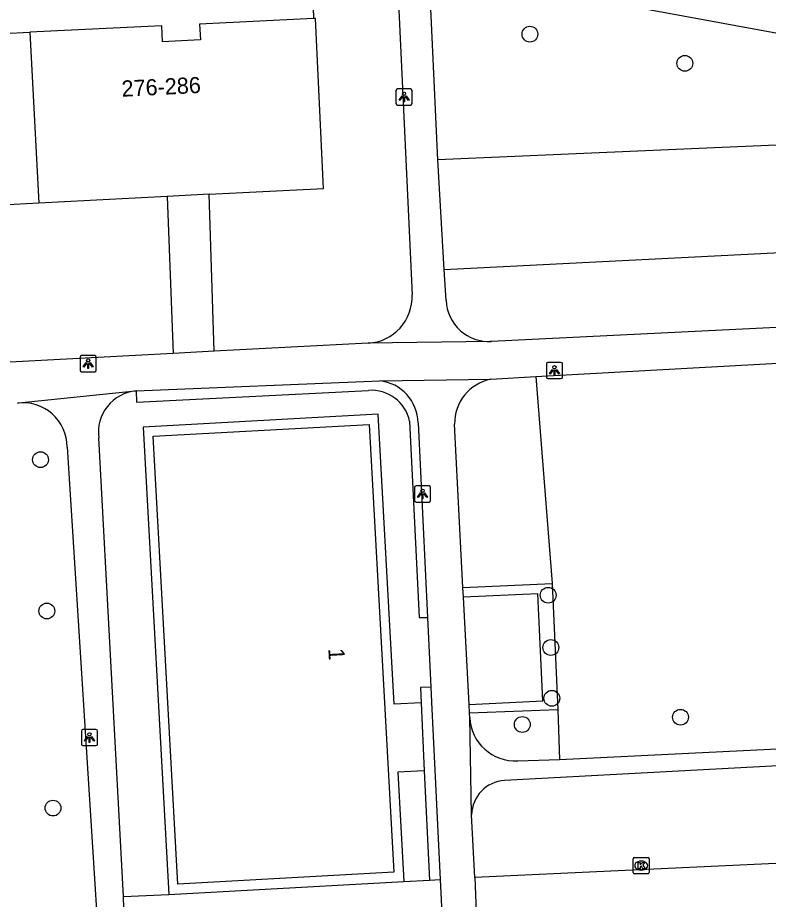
# Model space of a CAD drawing. Extents: x 161084 to 161928, y 385355 to 386522.
# Drawn here: x 161295.2 to 161341.7, y 385391.3 to 385445.9 of the extents above; entities that cross this region are included whole.
import ezdxf

# ---------------------------------------------------------------- set-up
doc = ezdxf.new("R2010")
doc.units = 0
for name, color, linetype in [('IMGEO_Boom', 7, 'Continuous'), ('IMGEO_Groenvoorziening', 7, 'Continuous'), ('IMGEO_Haag', 7, 'Continuous'), ('IMGEO_Kolk', 7, 'Continuous'), ('IMGEO_Lichtpunt', 7, 'Continuous'), ('IMGEO_Pand', 7, 'Continuous'), ('IMGEO_Pand_nummerreeks', 7, 'Continuous'), ('IMGEO_Parkeervlak_open', 7, 'Continuous'), ('IMGEO_Rijbaan_lokaal_open', 7, 'Continuous'), ('IMGEO_Voetpad_open', 7, 'Continuous')]:
    doc.layers.add(name, color=color, linetype=linetype)

msp = doc.modelspace()

# ---------------------------------------------------------------- linework, layer by layer
at = {"layer": 'IMGEO_Boom'}
for centre in [(161326.925, 385444.923), (161336.513, 385443.114), (161296.638, 385418.575), (161328.055, 385410.181), (161297.028, 385409.204), (161328.221, 385406.942), (161328.284, 385403.801), (161326.452, 385402.175), (161336.247, 385402.627), (161297.406, 385397.002)]:
    msp.add_circle(centre, 0.489, dxfattribs=at)
at = {"layer": 'IMGEO_Groenvoorziening'}
for points in [[(161370.714, 385439.291), (161321.228, 385437.144)], [(161321.624, 385430.341), (161370.59, 385432.827)], [(161327.282, 385423.72), (161328.3, 385410.901)], [(161328.656, 385403.078), (161328.751, 385400.019)]]:
    msp.add_lwpolyline(points, dxfattribs=at)
at = {"layer": 'IMGEO_Haag'}
for points in [[(161322.781, 385410.662), (161328.3, 385410.901)], [(161328.3, 385410.901), (161328.656, 385403.078)], [(161328.656, 385403.078), (161323.183, 385402.882)]]:
    msp.add_lwpolyline(points, dxfattribs=at)
at = {"layer": 'IMGEO_Kolk'}
for p, q in [((161333.388, 385393.94), (161334.24, 385393.94)), ((161333.313, 385393.014), (161333.313, 385393.866)), ((161333.801, 385393.72), (161333.826, 385393.72)), ((161334.314, 385393.866), (161334.314, 385393.014)), ((161334.24, 385392.94), (161333.388, 385392.94)), ((161333.824, 385393.16), (161333.799, 385393.16))]:
    msp.add_line(p, q, dxfattribs=at)
for points in [[(161333.388, 385393.94), (161334.24, 385393.94)], [(161333.313, 385393.014), (161333.313, 385393.866)], [(161333.634, 385393.64), (161333.757, 385393.64), (161333.757, 385393.489), (161333.887, 385393.64), (161334.051, 385393.64), (161333.905, 385393.489), (161334.058, 385393.24), (161333.906, 385393.24), (161333.821, 385393.404), (161333.757, 385393.337), (161333.757, 385393.24), (161333.634, 385393.24), (161333.634, 385393.64)], [(161334.314, 385393.866), (161334.314, 385393.014)], [(161334.24, 385392.94), (161333.388, 385392.94)]]:
    msp.add_lwpolyline(points, dxfattribs=at)
for centre, start, end in [((161333.39, 385393.864), 91.552, 178.448), ((161333.39, 385393.864), 91.552, 178.448), ((161334.238, 385393.864), 1.552, 88.448), ((161334.238, 385393.864), 1.552, 88.448), ((161333.39, 385393.016), 181.552, 268.448), ((161333.39, 385393.016), 181.552, 268.448), ((161334.238, 385393.016), 271.552, 358.448), ((161334.238, 385393.016), 271.552, 358.448)]:
    msp.add_arc(centre, 0.0765, start, end, dxfattribs=at)
for centre, major_axis, ratio, start_param, end_param in [((161333.8, 385393.44), (-0.387, 0.002), 0.722429, 4.712389, 7.853982), ((161333.825, 385393.44), (-0.39, 0.002), 0.717154, 1.570796, 4.712389)]:
    msp.add_ellipse(centre, major_axis=major_axis, ratio=ratio, start_param=start_param, end_param=end_param, dxfattribs=at)
at = {"layer": 'IMGEO_Lichtpunt'}
for p, q in [((161318.636, 385441.434), (161318.636, 385440.627)), ((161318.636, 385441.434), (161318.636, 385440.627)), ((161319.538, 385441.529), (161318.73, 385441.529)), ((161319.538, 385441.529), (161318.73, 385441.529)), ((161319.632, 385440.627), (161319.632, 385441.434)), ((161319.632, 385440.627), (161319.632, 385441.434)), ((161318.73, 385440.533), (161319.538, 385440.533)), ((161318.73, 385440.533), (161319.538, 385440.533)), ((161299.99, 385425.019), (161299.182, 385425.019)), ((161299.99, 385425.019), (161299.182, 385425.019)), ((161299.088, 385424.924), (161299.088, 385424.117)), ((161299.088, 385424.924), (161299.088, 385424.117)), ((161300.084, 385424.117), (161300.084, 385424.924)), ((161300.084, 385424.117), (161300.084, 385424.924)), ((161327.944, 385424.501), (161327.944, 385423.694)), ((161327.944, 385424.501), (161327.944, 385423.694)), ((161328.846, 385424.596), (161328.038, 385424.596)), ((161328.846, 385424.596), (161328.038, 385424.596)), ((161328.94, 385423.694), (161328.94, 385424.501)), ((161328.94, 385423.694), (161328.94, 385424.501)), ((161299.182, 385424.023), (161299.99, 385424.023)), ((161299.182, 385424.023), (161299.99, 385424.023)), ((161328.038, 385423.6), (161328.846, 385423.6)), ((161328.038, 385423.6), (161328.846, 385423.6)), ((161319.783, 385416.851), (161319.783, 385416.044)), ((161319.783, 385416.851), (161319.783, 385416.044)), ((161320.685, 385416.946), (161319.877, 385416.946)), ((161320.685, 385416.946), (161319.877, 385416.946)), ((161320.779, 385416.044), (161320.779, 385416.851)), ((161320.779, 385416.044), (161320.779, 385416.851)), ((161319.877, 385415.95), (161320.685, 385415.95)), ((161319.877, 385415.95), (161320.685, 385415.95)), ((161299.165, 385401.773), (161299.165, 385400.966)), ((161299.165, 385401.773), (161299.165, 385400.966)), ((161300.067, 385401.868), (161299.259, 385401.868)), ((161300.067, 385401.868), (161299.259, 385401.868)), ((161300.161, 385400.966), (161300.161, 385401.773)), ((161300.161, 385400.966), (161300.161, 385401.773)), ((161299.259, 385400.872), (161300.067, 385400.872)), ((161299.259, 385400.872), (161300.067, 385400.872))]:
    msp.add_line(p, q, dxfattribs=at)
for points in [[(161319.01, 385441.098), (161319.049, 385441.07), (161318.861, 385440.808), (161318.823, 385440.835), (161319.01, 385441.098)], [(161319.112, 385441.05), (161319.159, 385441.05), (161319.159, 385440.728), (161319.112, 385440.728), (161319.112, 385441.05)], [(161319.222, 385441.07), (161319.26, 385441.097), (161319.447, 385440.835), (161319.408, 385440.807), (161319.222, 385441.07)], [(161299.462, 385424.588), (161299.501, 385424.56), (161299.313, 385424.298), (161299.275, 385424.325), (161299.462, 385424.588)], [(161299.564, 385424.54), (161299.611, 385424.54), (161299.611, 385424.218), (161299.564, 385424.218), (161299.564, 385424.54)], [(161299.674, 385424.56), (161299.712, 385424.587), (161299.899, 385424.325), (161299.86, 385424.297), (161299.674, 385424.56)], [(161328.318, 385424.165), (161328.357, 385424.137), (161328.169, 385423.875), (161328.131, 385423.902), (161328.318, 385424.165)], [(161328.42, 385424.117), (161328.467, 385424.117), (161328.467, 385423.795), (161328.42, 385423.795), (161328.42, 385424.117)], [(161328.53, 385424.137), (161328.568, 385424.164), (161328.755, 385423.902), (161328.716, 385423.874), (161328.53, 385424.137)], [(161320.157, 385416.515), (161320.196, 385416.487), (161320.008, 385416.225), (161319.97, 385416.252), (161320.157, 385416.515)], [(161320.259, 385416.467), (161320.306, 385416.467), (161320.306, 385416.145), (161320.259, 385416.145), (161320.259, 385416.467)], [(161320.369, 385416.487), (161320.407, 385416.514), (161320.594, 385416.252), (161320.555, 385416.224), (161320.369, 385416.487)], [(161299.539, 385401.437), (161299.578, 385401.409), (161299.39, 385401.147), (161299.352, 385401.174), (161299.539, 385401.437)], [(161299.641, 385401.389), (161299.688, 385401.389), (161299.688, 385401.067), (161299.641, 385401.067), (161299.641, 385401.389)], [(161299.751, 385401.409), (161299.789, 385401.436), (161299.976, 385401.174), (161299.937, 385401.146), (161299.751, 385401.409)]]:
    msp.add_lwpolyline(points, dxfattribs=at)
for centre in [(161319.135, 385441.232), (161299.587, 385424.722), (161328.443, 385424.299), (161320.282, 385416.649), (161299.664, 385401.571)]:
    msp.add_circle(centre, 0.0994, dxfattribs=at)
for centre, start, end in [((161318.73, 385441.434), 90, 180), ((161318.73, 385441.434), 90, 180), ((161319.538, 385441.434), 0, 90), ((161319.538, 385441.434), 0, 90), ((161318.73, 385440.627), 180, 270), ((161318.73, 385440.627), 180, 270), ((161319.538, 385440.627), 270, 0), ((161319.538, 385440.627), 270, 360), ((161299.182, 385424.924), 90, 180), ((161299.182, 385424.924), 90, 180), ((161299.99, 385424.924), 0, 90), ((161299.99, 385424.924), 0, 90), ((161328.038, 385424.501), 90, 180), ((161328.038, 385424.501), 90, 180), ((161328.846, 385424.501), 0, 90), ((161328.846, 385424.501), 0, 90), ((161299.182, 385424.117), 180, 270), ((161299.182, 385424.117), 180, 270), ((161299.99, 385424.117), 270, 0), ((161299.99, 385424.117), 270, 360), ((161328.038, 385423.694), 180, 270), ((161328.038, 385423.694), 180, 270), ((161328.846, 385423.694), 270, 0), ((161328.846, 385423.694), 270, 360), ((161319.877, 385416.851), 90, 180), ((161319.877, 385416.851), 90, 180), ((161320.685, 385416.851), 0, 90), ((161320.685, 385416.851), 0, 90), ((161319.877, 385416.044), 180, 270), ((161319.877, 385416.044), 180, 270), ((161320.685, 385416.044), 270, 0), ((161320.685, 385416.044), 270, 360), ((161299.259, 385401.773), 90, 180), ((161299.259, 385401.773), 90, 180), ((161300.067, 385401.773), 0, 90), ((161300.067, 385401.773), 0, 90), ((161299.259, 385400.966), 180, 270), ((161299.259, 385400.966), 180, 270), ((161300.067, 385400.966), 270, 0), ((161300.067, 385400.966), 270, 360)]:
    msp.add_arc(centre, 0.0946, start, end, dxfattribs=at)
at = {"layer": 'IMGEO_Pand'}
for points in [[(161313.53, 385445.893), (161306.48, 385445.551), (161306.528, 385444.567), (161304.195, 385444.453), (161304.147, 385445.437), (161295.975, 385445.04)], [(161307.077, 385435.005), (161314.158, 385435.375), (161313.659, 385445.899), (161313.53, 385445.893)], [(161277.131, 385444.184), (161285.396, 385444.625), (161285.452, 385443.586), (161287.852, 385443.714), (161287.803, 385444.643), (161295.975, 385445.04)], [(161295.975, 385445.04), (161296.529, 385434.453)], [(161304.483, 385434.869), (161296.529, 385434.453)], [(161307.077, 385435.005), (161304.483, 385434.869)], [(161296.529, 385434.453), (161288.111, 385434.013)], [(161316.966, 385420.763), (161318.493, 385393.025), (161305.134, 385392.29), (161303.617, 385420.029), (161316.966, 385420.763)]]:
    msp.add_lwpolyline(points, dxfattribs=at)
at = {"layer": 'IMGEO_Parkeervlak_open'}
for points in [[(161323.155, 385403.422), (161327.715, 385403.635), (161327.418, 385410.262), (161322.812, 385410.063)], [(161320.702, 385392.546), (161321.373, 385392.583)]]:
    msp.add_lwpolyline(points, dxfattribs=at)
at = {"layer": 'IMGEO_Rijbaan_lokaal_open'}
for points in [[(161379.519, 385395.37), (161379.372, 385395.299), (161323.526, 385392.708)], [(161323.526, 385392.708), (161323.674, 385388.452)]]:
    msp.add_lwpolyline(points, dxfattribs=at)
at = {"layer": 'IMGEO_Voetpad_open'}
for points in [[(161313.28, 385453.877), (161313.53, 385445.893)], [(161318.737, 385448.213), (161319.633, 385428.79)], [(161370.804, 385439.731), (161323.607, 385448.409), (161322.906, 385448.466)], [(161321.228, 385437.144), (161320.77, 385446.952)], [(161321.624, 385430.341), (161321.228, 385437.144)], [(161304.483, 385434.869), (161304.852, 385425.15)], [(161307.393, 385425.285), (161307.077, 385435.005)], [(161321.737, 385428.437), (161321.624, 385430.341)], [(161346.813, 385426.983), (161324.55, 385425.894)], [(161327.282, 385423.72), (161371.881, 385426.171)], [(161316.909, 385425.792), (161307.393, 385425.285)], [(161324.55, 385425.894), (161324.461, 385425.883), (161316.909, 385425.792)], [(161304.852, 385425.15), (161288.506, 385424.279)], [(161307.393, 385425.285), (161304.852, 385425.15)], [(161302.549, 385422.828), (161317.628, 385423.461)], [(161317.628, 385423.461), (161324.496, 385423.565)], [(161324.496, 385423.565), (161327.282, 385423.72)], [(161295.221, 385422.083), (161295.289, 385422.097), (161302.496, 385422.83), (161302.549, 385422.828)], [(161302.549, 385422.828), (161302.583, 385422.133), (161316.928, 385422.862)], [(161320.187, 385403.526), (161318.522, 385403.434), (161317.53, 385421.395), (161302.984, 385420.595), (161304.569, 385391.657)], [(161319.481, 385420.953), (161320.069, 385408.806), (161320.586, 385408.806)], [(161320.001, 385420.857), (161320.586, 385408.806)], [(161322.781, 385410.662), (161322.259, 385420.772)], [(161301.769, 385391.518), (161300.244, 385419.936)], [(161298.278, 385419.359), (161300.252, 385388.395)], [(161322.812, 385410.063), (161322.781, 385410.662)], [(161323.155, 385403.422), (161322.812, 385410.063)], [(161320.586, 385408.806), (161320.795, 385404.495)], [(161320.795, 385404.495), (161320.143, 385404.471), (161320.187, 385403.526)], [(161320.795, 385404.495), (161320.84, 385403.562), (161321.045, 385399.347), (161321.373, 385392.583)], [(161320.187, 385403.526), (161320.385, 385399.311)], [(161323.183, 385402.882), (161323.155, 385403.422)], [(161323.198, 385402.602), (161323.183, 385402.882)], [(161323.318, 385396.593), (161323.198, 385402.602)], [(161328.751, 385400.019), (161372.994, 385402.172)], [(161326.169, 385399.923), (161328.751, 385400.019)], [(161345.094, 385397.755), (161344.972, 385399.766), (161325.358, 385398.703)], [(161320.385, 385399.311), (161318.755, 385399.221), (161319.128, 385392.459)], [(161320.385, 385399.311), (161320.702, 385392.546)], [(161323.526, 385392.708), (161323.318, 385396.593)], [(161304.569, 385391.657), (161319.128, 385392.459)], [(161319.128, 385392.459), (161320.702, 385392.546)], [(161321.373, 385392.583), (161321.557, 385388.794)], [(161301.769, 385391.518), (161304.569, 385391.657)], [(161301.86, 385388.681), (161301.769, 385391.518)]]:
    msp.add_lwpolyline(points, dxfattribs=at)
for centre, radius, start, end in [((161316.766, 385428.658), 2.87, 272.8473, 2.6357), ((161324.406, 385428.562), 2.672, 182.6769, 273.0948), ((161317.332, 385420.808), 2.67, 1.0565, 83.6287), ((161325.097, 385420.792), 2.838, 102.22, 180.3954), ((161302.775, 385420.283), 2.555, 95.083, 187.8055), ((161317.123, 385420.461), 2.409, 11.789, 94.6366), ((161295.54, 385419.364), 2.738, 359.904, 96.6895), ((161326.023, 385402.748), 2.829, 182.9629, 272.9541), ((161325.469, 385396.554), 2.152, 92.9687, 178.964)]:
    msp.add_arc(centre, radius, start, end, dxfattribs=at)

# ---------------------------------------------------------------- texts
at = {"layer": 'IMGEO_Pand_nummerreeks'}
for s, rotation, p in [('276-286', 2.796, (161301.677, 385441.046)), ('1', 273.151, (161314.446, 385406.875))]:
    msp.add_text(s, height=1, rotation=rotation, dxfattribs=at).set_placement(p)

doc.saveas('drawing.dxf')
